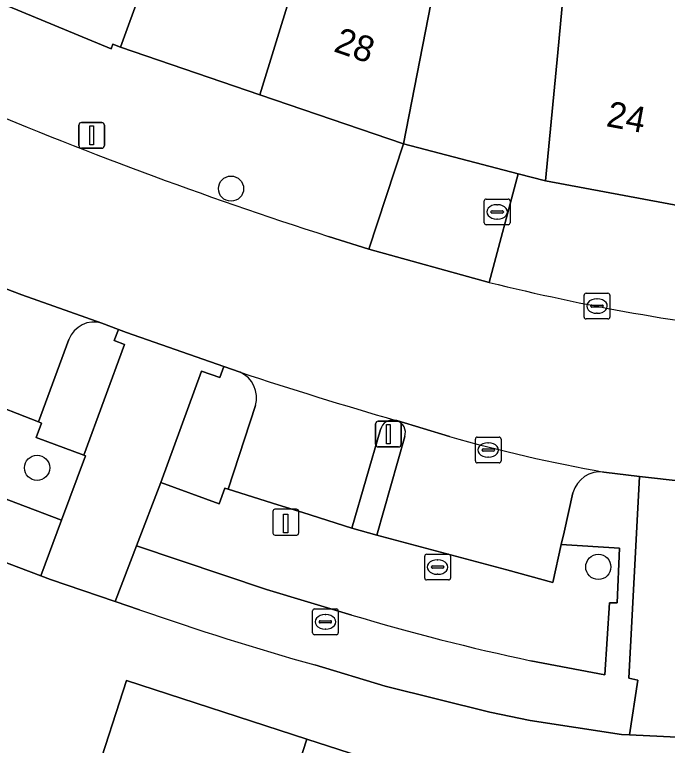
# Model space of a CAD drawing. Extents: x 163008 to 163854, y 382777 to 383982.
# Drawn here: x 163247.57 to 163272.93, y 383446.79 to 383475.17 of the extents above; entities that cross this region are included whole.
import ezdxf

# ---------------------------------------------------------------- set-up
doc = ezdxf.new("R2010")
doc.units = 0
for name, color, linetype in [('IMGEO_Boom', 7, 'Continuous'), ('IMGEO_Brandkraan', 7, 'Continuous'), ('IMGEO_Erf', 7, 'Continuous'), ('IMGEO_Groenvoorziening', 7, 'Continuous'), ('IMGEO_Kolk', 7, 'Continuous'), ('IMGEO_Laadpaal', 7, 'Continuous'), ('IMGEO_Lichtmast', 7, 'Continuous'), ('IMGEO_Pand', 7, 'Continuous'), ('IMGEO_Pand_nummerreeks', 7, 'Continuous'), ('IMGEO_Parkeervlak_open', 7, 'Continuous'), ('IMGEO_Rijbaan_lokaal_open', 7, 'Continuous'), ('IMGEO_Rioolput', 7, 'Continuous'), ('IMGEO_Voetpad_open', 7, 'Continuous')]:
    doc.layers.add(name, color=color, linetype=linetype)

msp = doc.modelspace()

# ---------------------------------------------------------------- linework, layer by layer
at = {"layer": 'IMGEO_Boom'}
for centre in [(163255.977, 383468.414), (163248.44, 383457.568), (163270.251, 383453.719)]:
    msp.add_circle(centre, 0.489, dxfattribs=at)
at = {"layer": 'IMGEO_Brandkraan'}
for p, q in [((163265.818, 383467.084), (163265.818, 383467.936)), ((163265.893, 383468.01), (163266.745, 383468.01)), ((163266.819, 383467.936), (163266.819, 383467.084)), ((163266.12, 383467.553), (163266.518, 383467.553)), ((163266.306, 383467.79), (163266.331, 383467.79)), ((163266.077, 383467.504), (163266.077, 383467.516)), ((163266.515, 383467.467), (163266.117, 383467.467)), ((163266.561, 383467.516), (163266.561, 383467.504)), ((163266.745, 383467.01), (163265.893, 383467.01)), ((163266.329, 383467.23), (163266.304, 383467.23)), ((163259.144, 383451.159), (163259.144, 383452.011)), ((163259.219, 383452.085), (163260.071, 383452.085)), ((163260.145, 383452.011), (163260.145, 383451.159)), ((163259.632, 383451.865), (163259.657, 383451.865)), ((163259.403, 383451.579), (163259.403, 383451.591)), ((163259.841, 383451.542), (163259.443, 383451.542)), ((163259.446, 383451.628), (163259.844, 383451.628)), ((163259.887, 383451.591), (163259.887, 383451.579)), ((163260.071, 383451.085), (163259.219, 383451.085)), ((163259.655, 383451.305), (163259.63, 383451.305))]:
    msp.add_line(p, q, dxfattribs=at)
for points in [[(163265.818, 383467.084), (163265.818, 383467.936)], [(163265.893, 383468.01), (163266.745, 383468.01)], [(163266.819, 383467.936), (163266.819, 383467.084)], [(163266.745, 383467.01), (163265.893, 383467.01)], [(163259.144, 383451.159), (163259.144, 383452.011)], [(163259.219, 383452.085), (163260.071, 383452.085)], [(163260.145, 383452.011), (163260.145, 383451.159)], [(163260.071, 383451.085), (163259.219, 383451.085)]]:
    msp.add_lwpolyline(points, dxfattribs=at)
for centre, radius, start, end in [((163265.895, 383467.934), 0.0765, 91.552, 178.448), ((163265.895, 383467.934), 0.0765, 91.552, 178.448), ((163266.743, 383467.934), 0.0765, 1.552, 88.448), ((163266.743, 383467.934), 0.0765, 1.552, 88.448), ((163266.117, 383467.513), 0.0403, 85.8775, 175.7526), ((163266.522, 383467.515), 0.0386, 1.7309, 96.639), ((163266.114, 383467.503), 0.0366, 178.938, 274.7102), ((163266.518, 383467.51), 0.043, 264.8664, 352.4533), ((163265.895, 383467.086), 0.0765, 181.552, 268.448), ((163265.895, 383467.086), 0.0765, 181.552, 268.448), ((163266.743, 383467.086), 0.0765, 271.552, 358.448), ((163266.743, 383467.086), 0.0765, 271.552, 358.448), ((163259.221, 383452.009), 0.0765, 91.552, 178.448), ((163259.221, 383452.009), 0.0765, 91.552, 178.448), ((163260.069, 383452.009), 0.0765, 1.552, 88.448), ((163260.069, 383452.009), 0.0765, 1.552, 88.448), ((163259.443, 383451.588), 0.0403, 85.8775, 175.7526), ((163259.44, 383451.578), 0.0366, 178.938, 274.7102), ((163259.844, 383451.585), 0.043, 264.8664, 352.4533), ((163259.848, 383451.59), 0.0386, 1.7309, 96.639), ((163259.221, 383451.161), 0.0765, 181.552, 268.448), ((163259.221, 383451.161), 0.0765, 181.552, 268.448), ((163260.069, 383451.161), 0.0765, 271.552, 358.448), ((163260.069, 383451.161), 0.0765, 271.552, 358.448)]:
    msp.add_arc(centre, radius, start, end, dxfattribs=at)
for centre, major_axis, ratio, start_param, end_param in [((163266.305, 383467.51), (-0.387, 0.002), 0.722429, 4.712389, 7.853982), ((163266.33, 383467.51), (-0.39, 0.002), 0.717154, 1.570796, 4.712389), ((163259.631, 383451.585), (-0.387, 0.002), 0.722429, 4.712389, 7.853982), ((163259.656, 383451.585), (-0.39, 0.002), 0.717154, 1.570796, 4.712389)]:
    msp.add_ellipse(centre, major_axis=major_axis, ratio=ratio, start_param=start_param, end_param=end_param, dxfattribs=at)
at = {"layer": 'IMGEO_Erf'}
for points in [[(163252.42, 383452.057), (163251.479, 383452.377), (163248.961, 383453.232), (163248.585, 383453.373), (163246.486, 383454.162), (163244.158, 383455.072), (163242.184, 383439.042)], [(163280.296, 383433.809), (163273.459, 383434.249), (163273.619, 383439.566), (163273.78, 383442.078), (163273.789, 383442.212), (163274.101, 383447.067), (163271.465, 383447.191), (163271.152, 383447.205), (163267.602, 383447.752), (163266.031, 383448.07), (163261.961, 383449.092), (163259.237, 383449.91)]]:
    msp.add_lwpolyline(points, dxfattribs=at)
msp.add_lwpolyline([(163269.737, 383434.489), (163268.684, 383431.24), (163261.724, 383433.494), (163255.224, 383435.6), (163248.373, 383437.819), (163249.611, 383441.642), (163249.449, 383441.694), (163251.915, 383449.304), (163258.926, 383447.032), (163265.578, 383444.877), (163272.388, 383442.67), (163270.847, 383437.914), (163269.953, 383435.156)], close=True, dxfattribs=at)
msp.add_arc((163288.045, 383553.275), 107.304, 250.60981, 254.42676, dxfattribs=at)
at = {"layer": 'IMGEO_Groenvoorziening'}
msp.add_lwpolyline([(163248.49, 383459.355), (163241.919, 383461.914), (163241.797, 383461.962), (163241.577, 383461.424), (163240.301, 383462.006), (163239.098, 383459.521), (163240.077, 383459.09), (163241.06, 383458.681), (163242.105, 383458.296), (163249.384, 383455.529), (163250.327, 383458.033), (163250.259, 383458.058), (163248.401, 383458.743), (163248.615, 383459.306)], close=True, dxfattribs=at)
for points in [[(163261.648, 383454.954), (163260.676, 383455.23), (163258.763, 383455.826), (163257.802, 383456.13), (163255.868, 383456.743), (163255.739, 383456.784), (163255.52, 383456.163), (163253.243, 383456.999), (163252.304, 383454.532), (163257.354, 383452.838), (163260.668, 383451.85)], [(163267.631, 383450.074), (163270.507, 383449.528), (163270.689, 383452.324), (163270.987, 383452.321), (163271.071, 383454.451), (163268.812, 383454.586), (163268.483, 383453.108), (163266.697, 383453.604), (163261.648, 383454.954)]]:
    msp.add_lwpolyline(points, dxfattribs=at)
msp.add_arc((163286.275, 383537.706), 89.594, 253.39274, 257.98943, dxfattribs=at)
at = {"layer": 'IMGEO_Kolk'}
for p, q in [((163269.699, 383463.424), (163269.699, 383464.276)), ((163269.774, 383464.35), (163270.626, 383464.35)), ((163270.7, 383464.276), (163270.7, 383463.424)), ((163269.958, 383463.844), (163269.958, 383463.856)), ((163270.001, 383463.893), (163270.399, 383463.893)), ((163270.187, 383464.13), (163270.212, 383464.13)), ((163270.442, 383463.856), (163270.442, 383463.844)), ((163270.396, 383463.807), (163269.998, 383463.807)), ((163270.626, 383463.35), (163269.774, 383463.35)), ((163270.21, 383463.57), (163270.185, 383463.57)), ((163265.548, 383458.76), (163266.4, 383458.76)), ((163265.473, 383457.834), (163265.473, 383458.686)), ((163265.961, 383458.54), (163265.986, 383458.54)), ((163266.474, 383458.686), (163266.474, 383457.834)), ((163265.732, 383458.254), (163265.732, 383458.266)), ((163266.17, 383458.217), (163265.772, 383458.217)), ((163265.775, 383458.303), (163266.173, 383458.303)), ((163266.216, 383458.266), (163266.216, 383458.254)), ((163265.984, 383457.98), (163265.959, 383457.98)), ((163266.4, 383457.76), (163265.548, 383457.76))]:
    msp.add_line(p, q, dxfattribs=at)
for points in [[(163269.699, 383463.424), (163269.699, 383464.276)], [(163269.774, 383464.35), (163270.626, 383464.35)], [(163270.7, 383464.276), (163270.7, 383463.424)], [(163270.626, 383463.35), (163269.774, 383463.35)], [(163265.548, 383458.76), (163266.4, 383458.76)], [(163265.473, 383457.834), (163265.473, 383458.686)], [(163266.474, 383458.686), (163266.474, 383457.834)], [(163266.4, 383457.76), (163265.548, 383457.76)]]:
    msp.add_lwpolyline(points, dxfattribs=at)
for centre, radius, start, end in [((163269.776, 383464.274), 0.0765, 91.552, 178.448), ((163269.776, 383464.274), 0.0765, 91.552, 178.448), ((163270.624, 383464.274), 0.0765, 1.552, 88.448), ((163270.624, 383464.274), 0.0765, 1.552, 88.448), ((163269.998, 383463.853), 0.0403, 85.8775, 175.7526), ((163270.403, 383463.855), 0.0386, 1.7309, 96.639), ((163269.995, 383463.843), 0.0366, 178.938, 274.7102), ((163270.399, 383463.85), 0.043, 264.8664, 352.4533), ((163269.776, 383463.426), 0.0765, 181.552, 268.448), ((163269.776, 383463.426), 0.0765, 181.552, 268.448), ((163270.624, 383463.426), 0.0765, 271.552, 358.448), ((163270.624, 383463.426), 0.0765, 271.552, 358.448), ((163265.55, 383458.684), 0.0765, 91.552, 178.448), ((163265.55, 383458.684), 0.0765, 91.552, 178.448), ((163266.398, 383458.684), 0.0765, 1.552, 88.448), ((163266.398, 383458.684), 0.0765, 1.552, 88.448), ((163265.772, 383458.263), 0.0403, 85.8775, 175.7526), ((163265.769, 383458.253), 0.0366, 178.938, 274.7102), ((163266.173, 383458.26), 0.043, 264.8664, 352.4533), ((163266.177, 383458.265), 0.0386, 1.7309, 96.639), ((163265.55, 383457.836), 0.0765, 181.552, 268.448), ((163265.55, 383457.836), 0.0765, 181.552, 268.448), ((163266.398, 383457.836), 0.0765, 271.552, 358.448), ((163266.398, 383457.836), 0.0765, 271.552, 358.448)]:
    msp.add_arc(centre, radius, start, end, dxfattribs=at)
for centre, major_axis, ratio, start_param, end_param in [((163270.186, 383463.85), (-0.387, 0.002), 0.722429, 4.712389, 7.853982), ((163270.211, 383463.85), (-0.39, 0.002), 0.717154, 1.570796, 4.712389), ((163265.96, 383458.26), (-0.387, 0.002), 0.722429, 4.712389, 7.853982), ((163265.985, 383458.26), (-0.39, 0.002), 0.717154, 1.570796, 4.712389)]:
    msp.add_ellipse(centre, major_axis=major_axis, ratio=ratio, start_param=start_param, end_param=end_param, dxfattribs=at)
at = {"layer": 'IMGEO_Laadpaal'}
for p, q in [((163258.522, 383455.957), (163257.681, 383455.957)), ((163258.522, 383455.957), (163257.681, 383455.957)), ((163257.606, 383455.873), (163257.606, 383455.032)), ((163257.606, 383455.873), (163257.606, 383455.032)), ((163258.606, 383455.041), (163258.606, 383455.882)), ((163258.606, 383455.041), (163258.606, 383455.882)), ((163257.69, 383454.957), (163258.531, 383454.957)), ((163257.69, 383454.957), (163258.531, 383454.957))]:
    msp.add_line(p, q, dxfattribs=at)
msp.add_lwpolyline([(163258.021, 383455.77), (163258.181, 383455.77), (163258.181, 383455.037), (163258.021, 383455.037), (163258.021, 383455.77)], dxfattribs=at)
for centre, start, end in [((163257.684, 383455.879), 92.4484, 184.2845), ((163257.684, 383455.879), 92.4484, 184.2845), ((163258.528, 383455.879), 2.4484, 94.2845), ((163258.528, 383455.879), 2.4484, 94.2845), ((163257.684, 383455.035), 182.4484, 274.2845), ((163257.684, 383455.035), 182.4484, 274.2845), ((163258.528, 383455.035), 272.4484, 4.2845), ((163258.528, 383455.035), 272.4484, 4.2845)]:
    msp.add_arc(centre, 0.0779, start, end, dxfattribs=at)
at = {"layer": 'IMGEO_Lichtmast'}
for p, q in [((163250.164, 383470.984), (163250.954, 383470.984)), ((163250.954, 383470.984), (163250.164, 383470.984)), ((163250.064, 383470.084), (163250.064, 383470.884)), ((163250.064, 383470.884), (163250.064, 383470.084)), ((163251.054, 383470.884), (163251.054, 383470.084)), ((163251.054, 383470.084), (163251.054, 383470.884)), ((163250.954, 383469.984), (163250.164, 383469.984)), ((163250.164, 383469.984), (163250.954, 383469.984)), ((163261.697, 383459.381), (163262.487, 383459.381)), ((163262.487, 383459.381), (163261.697, 383459.381)), ((163261.597, 383458.481), (163261.597, 383459.281)), ((163261.597, 383459.281), (163261.597, 383458.481)), ((163262.587, 383459.281), (163262.587, 383458.481)), ((163262.587, 383458.481), (163262.587, 383459.281)), ((163262.487, 383458.381), (163261.697, 383458.381)), ((163261.697, 383458.381), (163262.487, 383458.381))]:
    msp.add_line(p, q, dxfattribs=at)
for points in [[(163250.484, 383470.859), (163250.634, 383470.859), (163250.634, 383470.109), (163250.484, 383470.109), (163250.484, 383470.859)], [(163262.017, 383459.256), (163262.167, 383459.256), (163262.167, 383458.506), (163262.017, 383458.506), (163262.017, 383459.256)]]:
    msp.add_lwpolyline(points, dxfattribs=at)
for centre, start, end in [((163250.164, 383470.884), 90, 180), ((163250.164, 383470.884), 90, 180), ((163250.954, 383470.884), 0, 90), ((163250.954, 383470.884), 360, 90), ((163250.164, 383470.084), 180, 270), ((163250.164, 383470.084), 180, 270), ((163250.954, 383470.084), 270, 0), ((163250.954, 383470.084), 270, 0), ((163261.697, 383459.281), 90, 180), ((163261.697, 383459.281), 90, 180), ((163262.487, 383459.281), 0, 90), ((163262.487, 383459.281), 360, 90), ((163261.697, 383458.481), 180, 270), ((163261.697, 383458.481), 180, 270), ((163262.487, 383458.481), 270, 0), ((163262.487, 383458.481), 270, 0)]:
    msp.add_arc(centre, 0.1, start, end, dxfattribs=at)
at = {"layer": 'IMGEO_Pand'}
for points in [[(163255.101, 383483.306), (163252.605, 383484.404), (163254.083, 383487.53), (163252.108, 383488.52), (163245.709, 383476.329), (163245.647, 383476.205), (163251.319, 383473.847), (163251.378, 383474.021), (163251.687, 383473.915)], [(163259.475, 383479.804), (163259.547, 383480.009), (163258.733, 383480.288), (163256.777, 383480.958), (163257.459, 383482.949), (163258.383, 383485.646), (163258.236, 383485.704), (163257.818, 383485.869), (163256.256, 383486.484), (163255.101, 383483.306), (163251.687, 383473.915), (163257.096, 383472.063)], [(163264.283, 383478.39), (163264.777, 383480.963), (163265.021, 383482.232), (163264.628, 383482.366), (163263.475, 383482.761), (163263.061, 383481.55), (163260.405, 383482.459), (163259.547, 383480.009), (163259.475, 383479.804), (163257.096, 383472.063), (163262.68, 383470.15), (163263.636, 383475.058)], [(163274.629, 383475.579), (163274.699, 383476.098), (163275.172, 383479.601), (163271.83, 383480.193), (163271.606, 383480.233), (163269.469, 383480.611), (163268.991, 383477.057), (163268.671, 383473.696), (163268.196, 383468.718), (163273.545, 383467.715)], [(163258.926, 383447.032), (163251.915, 383449.304), (163249.449, 383441.694), (163249.611, 383441.642), (163248.373, 383437.819), (163255.224, 383435.6)], [(163258.926, 383447.032), (163255.224, 383435.6), (163261.724, 383433.494), (163265.578, 383444.877)]]:
    msp.add_lwpolyline(points, close=True, dxfattribs=at)
at = {"layer": 'IMGEO_Parkeervlak_open'}
for points in [[(163250.961, 383463.189), (163247.848, 383464.291), (163245.72, 383465.085), (163242.717, 383466.382)], [(163243.165, 383465.024), (163241.919, 383461.914), (163248.49, 383459.355), (163249.679, 383462.556)], [(163256.926, 383459.994), (163255.868, 383456.743), (163257.802, 383456.13), (163258.763, 383455.826), (163260.676, 383455.23), (163261.787, 383459.053)], [(163264.464, 383458.779), (163262.417, 383459.4)], [(163262.729, 383458.781), (163261.648, 383454.954), (163266.697, 383453.604), (163268.483, 383453.108), (163268.812, 383454.586), (163268.919, 383455.066), (163269.265, 383456.6)]]:
    msp.add_lwpolyline(points, dxfattribs=at)
for centre, radius, start, end in [((163250.66, 383462.185), 1.049, 73.2969, 159.2597), ((163310.644, 383626.1), 173.537, 251.76014, 253.85224), ((163255.888, 383460.296), 1.081, 343.7982, 65.9774), ((163262.262, 383458.935), 0.489, 75.9313, 166.0813), ((163262.263, 383458.934), 0.491, 341.815, 71.6848), ((163281.812, 383520.805), 64.406, 254.37423, 259.85816), ((163270.331, 383456.308), 1.106, 82.7516, 164.6943)]:
    msp.add_arc(centre, radius, start, end, dxfattribs=at)
at = {"layer": 'IMGEO_Rijbaan_lokaal_open'}
for points in [[(163266.263, 383490.878), (163265.73, 383488.128), (163265.624, 383487.579), (163265.558, 383487.243), (163264.628, 383482.366), (163265.021, 383482.232), (163264.777, 383480.963), (163264.283, 383478.39), (163263.636, 383475.058), (163262.68, 383470.15), (163267.138, 383468.993), (163268.196, 383468.718), (163268.671, 383473.696), (163268.991, 383477.057), (163269.469, 383480.611), (163270.677, 383486.749), (163272.411, 383497.83)], [(163230.407, 383472.363), (163233.775, 383470.618), (163236.298, 383469.364), (163239.93, 383467.627), (163240.85, 383467.218), (163242.717, 383466.382), (163245.72, 383465.085), (163247.848, 383464.291), (163250.961, 383463.189), (163251.598, 383462.94), (163251.909, 383462.819), (163255.693, 383461.504), (163256.328, 383461.283)], [(163266.01, 383464.771), (163261.332, 383466.06), (163259.763, 383466.556)], [(163270.471, 383457.405), (163271.847, 383457.228), (163275.321, 383456.845), (163275.604, 383456.817), (163276.215, 383456.757), (163276.662, 383456.725), (163277.301, 383462.761)], [(163262.381, 383459.41), (163262.417, 383459.4), (163264.464, 383458.779)]]:
    msp.add_lwpolyline(points, dxfattribs=at)
for centre, radius, start, end in [((163312.571, 383630.501), 172.24, 241.94967, 252.14569), ((163287.021, 383550.08), 87.859, 256.1639, 263.64823), ((163310.644, 383626.1), 173.537, 251.76014, 253.85224), ((163281.812, 383520.805), 64.406, 254.37423, 259.85816)]:
    msp.add_arc(centre, radius, start, end, dxfattribs=at)
at = {"layer": 'IMGEO_Rioolput'}
for p, q in [((163263.58, 383454.211), (163264.432, 383454.211)), ((163263.505, 383453.285), (163263.505, 383454.137)), ((163263.993, 383453.991), (163264.018, 383453.991)), ((163264.506, 383454.137), (163264.506, 383453.285)), ((163263.764, 383453.705), (163263.764, 383453.717)), ((163264.202, 383453.668), (163263.804, 383453.668)), ((163263.807, 383453.754), (163264.205, 383453.754)), ((163264.248, 383453.717), (163264.248, 383453.705)), ((163264.016, 383453.431), (163263.991, 383453.431)), ((163264.432, 383453.211), (163263.58, 383453.211))]:
    msp.add_line(p, q, dxfattribs=at)
for points in [[(163263.58, 383454.211), (163264.432, 383454.211)], [(163263.505, 383453.285), (163263.505, 383454.137)], [(163264.506, 383454.137), (163264.506, 383453.285)], [(163264.432, 383453.211), (163263.58, 383453.211)]]:
    msp.add_lwpolyline(points, dxfattribs=at)
for centre, radius, start, end in [((163263.582, 383454.135), 0.0765, 91.552, 178.448), ((163263.582, 383454.135), 0.0765, 91.552, 178.448), ((163264.43, 383454.135), 0.0765, 1.552, 88.448), ((163264.43, 383454.135), 0.0765, 1.552, 88.448), ((163263.804, 383453.714), 0.0403, 85.8775, 175.7526), ((163263.801, 383453.704), 0.0366, 178.938, 274.7102), ((163264.205, 383453.711), 0.043, 264.8664, 352.4533), ((163264.209, 383453.716), 0.0386, 1.7309, 96.639), ((163263.582, 383453.287), 0.0765, 181.552, 268.448), ((163263.582, 383453.287), 0.0765, 181.552, 268.448), ((163264.43, 383453.287), 0.0765, 271.552, 358.448), ((163264.43, 383453.287), 0.0765, 271.552, 358.448)]:
    msp.add_arc(centre, radius, start, end, dxfattribs=at)
for centre, major_axis, ratio, start_param, end_param in [((163263.992, 383453.711), (-0.387, 0.002), 0.722429, 4.712389, 7.853982), ((163264.017, 383453.711), (-0.39, 0.002), 0.717154, 1.570796, 4.712389)]:
    msp.add_ellipse(centre, major_axis=major_axis, ratio=ratio, start_param=start_param, end_param=end_param, dxfattribs=at)
at = {"layer": 'IMGEO_Voetpad_open'}
for points in [[(163259.763, 383466.556), (163261.332, 383466.06), (163262.68, 383470.15), (163257.096, 383472.063), (163251.687, 383473.915), (163251.378, 383474.021), (163251.319, 383473.847), (163245.647, 383476.205), (163245.709, 383476.329), (163240.575, 383478.903), (163234.946, 383481.726), (163234.081, 383482.172), (163229.131, 383484.819), (163227.067, 383481.003), (163231.576, 383478.493)], [(163213.708, 383469.953), (163218.261, 383467.552), (163221.969, 383465.635), (163226.041, 383463.508), (163230.338, 383461.314), (163236.671, 383458.234), (163238.419, 383457.383), (163238.571, 383457.309), (163240.642, 383456.413), (163241.659, 383456.026), (163243.741, 383455.235), (163244.158, 383455.072), (163246.486, 383454.162), (163248.585, 383453.373), (163249.384, 383455.529), (163242.105, 383458.296), (163241.06, 383458.681), (163240.077, 383459.09), (163239.098, 383459.521), (163240.301, 383462.006), (163241.577, 383461.424), (163241.797, 383461.962), (163241.919, 383461.914), (163243.165, 383465.024)], [(163310.182, 383464.679), (163307.126, 383464.876), (163306.231, 383464.933), (163300.805, 383465.282), (163293.832, 383465.73), (163286.418, 383466.207), (163279.066, 383466.68), (163273.545, 383467.715), (163268.196, 383468.718), (163267.138, 383468.993), (163266.01, 383464.771)], [(163251.598, 383462.94), (163250.961, 383463.189)], [(163249.679, 383462.556), (163248.49, 383459.355), (163248.615, 383459.306), (163248.401, 383458.743), (163250.259, 383458.058), (163251.837, 383462.358), (163251.43, 383462.517), (163251.598, 383462.94)], [(163256.328, 383461.283), (163255.693, 383461.504), (163255.54, 383461.078), (163254.836, 383461.323), (163253.243, 383456.999), (163255.52, 383456.163), (163255.739, 383456.784), (163255.868, 383456.743), (163256.926, 383459.994)], [(163262.417, 383459.4), (163262.381, 383459.41)], [(163261.787, 383459.053), (163260.676, 383455.23), (163261.648, 383454.954), (163262.729, 383458.781)], [(163259.237, 383449.91), (163261.961, 383449.092), (163266.031, 383448.07), (163267.602, 383447.752), (163271.152, 383447.205), (163271.465, 383447.191), (163271.792, 383449.324), (163271.432, 383449.395), (163271.847, 383457.228), (163270.471, 383457.405)], [(163269.265, 383456.6), (163268.919, 383455.066), (163268.812, 383454.586), (163271.071, 383454.451), (163270.987, 383452.321), (163270.689, 383452.324), (163270.507, 383449.528), (163267.631, 383450.074)], [(163252.304, 383454.532), (163251.479, 383452.377), (163252.42, 383452.057)], [(163260.668, 383451.85), (163257.354, 383452.838), (163252.304, 383454.532)]]:
    msp.add_lwpolyline(points, dxfattribs=at)
for points in [[(163267.138, 383468.993), (163262.68, 383470.15), (163261.332, 383466.06), (163266.01, 383464.771)], [(163255.693, 383461.504), (163251.909, 383462.819), (163251.598, 383462.94), (163251.43, 383462.517), (163251.837, 383462.358), (163250.259, 383458.058), (163250.327, 383458.033), (163249.384, 383455.529), (163248.585, 383453.373), (163248.961, 383453.232), (163251.479, 383452.377), (163252.304, 383454.532), (163253.243, 383456.999), (163254.836, 383461.323), (163255.54, 383461.078)], [(163275.604, 383456.817), (163275.321, 383456.845), (163271.847, 383457.228), (163271.432, 383449.395), (163271.792, 383449.324), (163271.465, 383447.191), (163274.101, 383447.067), (163274.348, 383451.687), (163274.512, 383453.87), (163275.414, 383453.779)]]:
    msp.add_lwpolyline(points, close=True, dxfattribs=at)
for centre, radius, start, end in [((163312.571, 383630.501), 172.24, 241.94967, 252.14569), ((163287.021, 383550.08), 87.859, 256.1639, 263.64823), ((163250.66, 383462.185), 1.049, 73.2969, 159.2597), ((163255.888, 383460.296), 1.081, 343.7982, 65.9774), ((163262.262, 383458.935), 0.489, 75.9313, 166.0813), ((163262.263, 383458.934), 0.491, 341.815, 71.6848), ((163270.331, 383456.308), 1.106, 82.7516, 164.6943), ((163288.045, 383553.275), 107.304, 250.60981, 254.42676), ((163286.275, 383537.706), 89.594, 253.39274, 257.98943)]:
    msp.add_arc(centre, radius, start, end, dxfattribs=at)

# ---------------------------------------------------------------- texts
at = {"layer": 'IMGEO_Pand_nummerreeks'}
for s, rotation, p in [('28', 341.0867, (163259.926, 383473.757)), ('24', 349.3831, (163270.523, 383470.845))]:
    msp.add_text(s, height=1, rotation=rotation, dxfattribs=at).set_placement(p)

doc.saveas('drawing.dxf')
